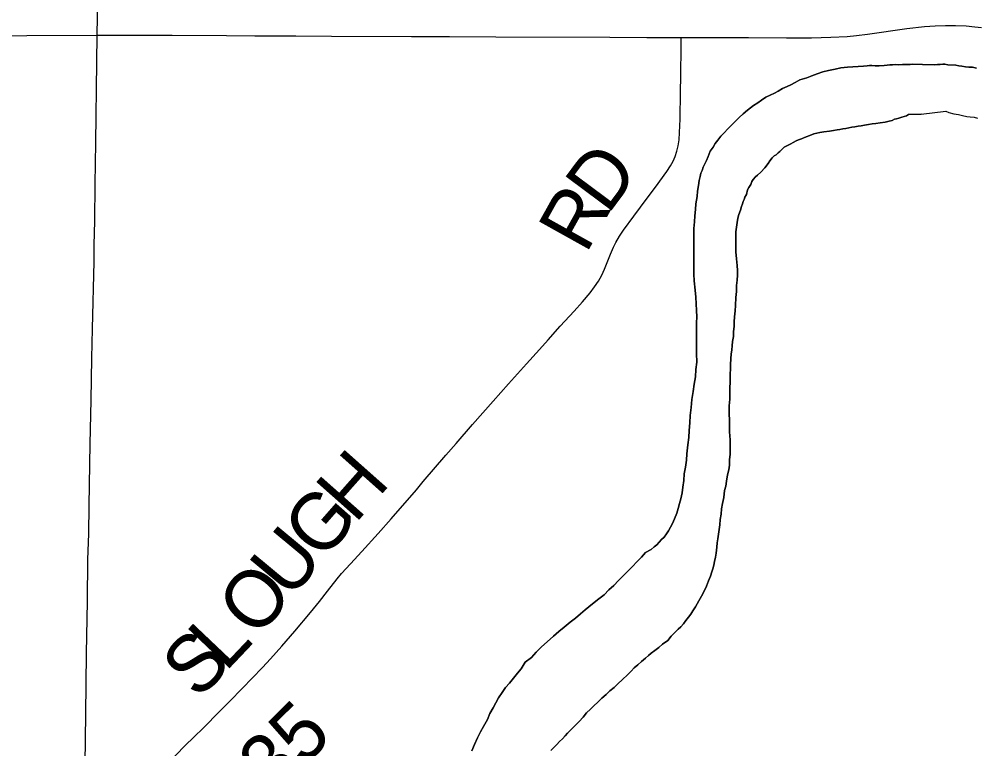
# Model space of a CAD drawing. Extents: x 2.1 to 73.9, y 4 to 26.
# Drawn here: x 45.0951 to 45.571, y 22.9914 to 23.3545 of the extents above; entities that cross this region are included whole.
import ezdxf

# ---------------------------------------------------------------- set-up
doc = ezdxf.new("R2010")
doc.units = 0
for name, color, linetype in [('GM_X_County_Road', 7, 'Continuous'), ('GM_X_Major_River', 7, 'Continuous'), ('GM_X_State_Route', 7, 'Continuous'), ('GM_X_Township_Road', 7, 'Continuous'), ('GM_X_Township_Road_Text', 7, 'Continuous')]:
    doc.layers.add(name, color=color, linetype=linetype)

msp = doc.modelspace()

# ---------------------------------------------------------------- linework, layer by layer
at = {"layer": 'GM_X_County_Road'}
for points in [[(45.13396, 23.34651), (45.13443, 23.37409), (45.135, 23.41791), (45.13565, 23.46205), (45.13596, 23.48723), (45.13647, 23.52204), (45.13721, 23.56151), (45.13784, 23.59569), (45.13829, 23.62739), (45.13897, 23.66314), (45.13954, 23.69017), (45.14, 23.71255), (45.14029, 23.72747), (45.14061, 23.74829), (45.14116, 23.77198), (45.14159, 23.79024), (45.14203, 23.81542), (45.14219, 23.82785), (45.14253, 23.84741)], [(45.12754, 22.94886), (45.12771, 22.95705), (45.12797, 22.98377), (45.12823, 23.00862), (45.12857, 23.03875), (45.12905, 23.06486), (45.12936, 23.08568), (45.12972, 23.09842), (45.12994, 23.11241), (45.13052, 23.14317), (45.13089, 23.16493), (45.1313, 23.18575), (45.13165, 23.20035), (45.13236, 23.23392), (45.13245, 23.24201), (45.13273, 23.25412), (45.13301, 23.27246), (45.13323, 23.29298), (45.13373, 23.33307), (45.13396, 23.34651)]]:
    msp.add_lwpolyline(points, dxfattribs=at)
at = {"layer": 'GM_X_Major_River'}
for points in [[(45.52139, 23.33129), (45.51968, 23.33151), (45.51854, 23.33153), (45.5174, 23.33136), (45.51549, 23.3312), (45.5075, 23.33056), (45.50426, 23.33024), (45.5014, 23.32971), (45.49815, 23.329), (45.49529, 23.32829), (45.49242, 23.32739), (45.48974, 23.32629), (45.48725, 23.32538), (45.48381, 23.32429), (45.48151, 23.323), (45.4794, 23.32189), (45.47748, 23.32097), (45.47519, 23.32006), (45.47307, 23.31876), (45.47116, 23.31765), (45.46905, 23.31674), (45.46694, 23.31563), (45.46482, 23.31414), (45.4629, 23.31285), (45.46079, 23.31155), (45.45771, 23.30932), (45.45559, 23.30745), (45.45366, 23.30558), (45.45173, 23.30371), (45.4496, 23.30166), (45.44786, 23.29979), (45.44631, 23.2981), (45.44457, 23.29623), (45.44302, 23.29435), (45.44166, 23.29267), (45.44068, 23.29078), (45.43913, 23.28891), (45.43814, 23.28626), (45.43734, 23.28418), (45.43656, 23.28249), (45.43577, 23.28079), (45.43517, 23.27928), (45.43458, 23.27796), (45.43417, 23.27626), (45.43376, 23.27417), (45.43334, 23.27171), (45.43292, 23.26887), (45.43268, 23.26621), (45.43206, 23.26261), (45.43182, 23.25977), (45.43158, 23.25673), (45.43135, 23.25369), (45.4311, 23.25028), (45.43104, 23.24629), (45.43098, 23.2423), (45.43099, 23.23128), (45.43112, 23.22767), (45.43126, 23.22425), (45.43176, 23.21968), (45.43208, 23.21625), (45.43222, 23.21283), (45.43236, 23.2096), (45.4325, 23.20637), (45.43245, 23.20333), (45.4324, 23.20029), (45.43236, 23.19744), (45.43231, 23.19459), (45.43246, 23.19155), (45.4324, 23.18813), (45.43252, 23.18376), (45.43209, 23.18016), (45.43184, 23.17655), (45.43121, 23.17295), (45.43077, 23.16916), (45.43014, 23.16518), (45.4297, 23.16119), (45.42925, 23.15721), (45.429, 23.15361), (45.42875, 23.14981), (45.42851, 23.14639), (45.42807, 23.1426), (45.42762, 23.13824), (45.42738, 23.13501), (45.42695, 23.1316), (45.42632, 23.12819), (45.42608, 23.12496), (45.42565, 23.12155), (45.42522, 23.11871), (45.42461, 23.11587), (45.424, 23.11341), (45.4232, 23.11095), (45.42259, 23.10868), (45.42141, 23.10585), (45.42042, 23.10358), (45.41944, 23.1017), (45.41846, 23.09981), (45.41748, 23.09831), (45.41632, 23.09681), (45.41497, 23.0955), (45.4138, 23.09419), (45.41264, 23.09288)], [(45.41264, 23.09288), (45.4138, 23.09419), (45.41497, 23.0955), (45.41632, 23.09681), (45.41748, 23.09831), (45.41846, 23.09981), (45.41944, 23.1017), (45.42042, 23.10358), (45.42141, 23.10585), (45.42259, 23.10868), (45.4232, 23.11095), (45.424, 23.11341), (45.42461, 23.11587), (45.42522, 23.11871), (45.42565, 23.12155), (45.42608, 23.12496), (45.42632, 23.12819), (45.42695, 23.1316), (45.42738, 23.13501), (45.42762, 23.13824), (45.42807, 23.1426), (45.42851, 23.14639), (45.42875, 23.14981), (45.429, 23.15361), (45.42925, 23.15721), (45.4297, 23.16119), (45.43014, 23.16518), (45.43077, 23.16916), (45.43121, 23.17295), (45.43184, 23.17655), (45.43209, 23.18016), (45.43252, 23.18376), (45.4324, 23.18813), (45.43246, 23.19155), (45.43231, 23.19459), (45.43236, 23.19744), (45.4324, 23.20029), (45.43245, 23.20333), (45.4325, 23.20637), (45.43236, 23.2096), (45.43222, 23.21283), (45.43208, 23.21625), (45.43176, 23.21968), (45.43126, 23.22425), (45.43112, 23.22767), (45.43099, 23.23128), (45.43098, 23.2423), (45.43104, 23.24629), (45.4311, 23.25028), (45.43135, 23.25369), (45.43158, 23.25673), (45.43182, 23.25977), (45.43206, 23.26261), (45.43268, 23.26621), (45.43292, 23.26887), (45.43334, 23.27171), (45.43376, 23.27417), (45.43417, 23.27626), (45.43458, 23.27796), (45.43517, 23.27928), (45.43577, 23.28079), (45.43656, 23.28249), (45.43734, 23.28418), (45.43814, 23.28626), (45.43913, 23.28891), (45.44068, 23.29078), (45.44166, 23.29267), (45.44302, 23.29435), (45.44457, 23.29623), (45.44631, 23.2981), (45.44786, 23.29979), (45.4496, 23.30166), (45.45173, 23.30371), (45.45366, 23.30558), (45.45559, 23.30745), (45.45771, 23.30932), (45.46079, 23.31155), (45.4629, 23.31285), (45.46482, 23.31414), (45.46694, 23.31563), (45.46905, 23.31674), (45.47116, 23.31765), (45.47307, 23.31876), (45.47519, 23.32006), (45.47748, 23.32097), (45.4794, 23.32189), (45.48151, 23.323), (45.48381, 23.32429), (45.48725, 23.32538), (45.48974, 23.32629), (45.49242, 23.32739), (45.49529, 23.32829), (45.49815, 23.329), (45.5014, 23.32971), (45.50426, 23.33024), (45.5075, 23.33056), (45.51549, 23.3312), (45.5174, 23.33136), (45.51854, 23.33153), (45.51968, 23.33151), (45.52139, 23.33129)], [(45.54486, 23.33196), (45.54004, 23.33214), (45.53871, 23.33197), (45.53681, 23.332), (45.53491, 23.33203), (45.53319, 23.33187), (45.53148, 23.33189), (45.52996, 23.33173), (45.52863, 23.33175), (45.52729, 23.33158), (45.52577, 23.33141), (45.52329, 23.33126), (45.52234, 23.33128), (45.52139, 23.33129)], [(45.52139, 23.33129), (45.52234, 23.33128), (45.52329, 23.33126), (45.52577, 23.33141), (45.52729, 23.33158), (45.52863, 23.33175), (45.52996, 23.33173), (45.53148, 23.33189), (45.53319, 23.33187), (45.53491, 23.33203), (45.53681, 23.332), (45.53871, 23.33197), (45.54004, 23.33214), (45.54486, 23.33196)], [(45.57178, 23.33017), (45.56989, 23.33059), (45.56799, 23.33064), (45.56629, 23.33087), (45.56458, 23.33111), (45.56307, 23.33134), (45.56155, 23.33156), (45.55757, 23.33185), (45.55606, 23.33208), (45.55511, 23.33211), (45.55378, 23.33195), (45.55245, 23.33198), (45.55093, 23.33183), (45.54486, 23.33196)], [(45.54486, 23.33196), (45.55093, 23.33183), (45.55245, 23.33198), (45.55378, 23.33195), (45.55511, 23.33211), (45.55606, 23.33208), (45.55757, 23.33185), (45.56155, 23.33156), (45.56307, 23.33134), (45.56458, 23.33111), (45.56629, 23.33087), (45.56799, 23.33064), (45.56989, 23.33059), (45.57178, 23.33017)], [(45.54429, 23.30717), (45.55661, 23.30871), (45.55812, 23.30811), (45.56057, 23.30747), (45.56284, 23.30704), (45.56492, 23.3066), (45.567, 23.30617), (45.5687, 23.30594), (45.57059, 23.3057), (45.57229, 23.30528)], [(45.54429, 23.30717), (45.55661, 23.30871), (45.55812, 23.30811), (45.56057, 23.30747), (45.56284, 23.30704), (45.56492, 23.3066), (45.567, 23.30617), (45.5687, 23.30594), (45.57059, 23.3057), (45.57229, 23.30528)], [(45.4488, 23.15462), (45.44867, 23.15842), (45.44873, 23.16203), (45.44897, 23.16545), (45.44902, 23.16868), (45.44906, 23.17134), (45.4491, 23.17362), (45.44914, 23.17589), (45.44917, 23.17798), (45.44939, 23.18026), (45.44924, 23.18254), (45.44948, 23.18558), (45.44971, 23.18786), (45.44993, 23.18994), (45.45015, 23.19203), (45.45037, 23.19411), (45.45079, 23.19658), (45.45083, 23.19905), (45.45106, 23.20151), (45.4511, 23.20398), (45.45133, 23.20645), (45.45157, 23.20929), (45.4518, 23.21195), (45.45205, 23.21594), (45.45229, 23.21897), (45.45234, 23.22201), (45.45257, 23.22467), (45.4528, 23.22713), (45.45283, 23.22941), (45.45268, 23.23189), (45.45236, 23.23531), (45.45203, 23.23874), (45.452, 23.24862), (45.45223, 23.25108), (45.45264, 23.25335), (45.45305, 23.25544), (45.45347, 23.25733), (45.45426, 23.25941), (45.45486, 23.2613), (45.45526, 23.26262), (45.45566, 23.26376), (45.45605, 23.2647), (45.45646, 23.26602), (45.45724, 23.26734), (45.45784, 23.26961), (45.45843, 23.27074), (45.45941, 23.27225), (45.46, 23.27376), (45.46059, 23.2747), (45.46175, 23.27601), (45.46271, 23.27694), (45.46445, 23.27843), (45.46638, 23.28049), (45.46813, 23.28275), (45.46891, 23.28406), (45.47008, 23.28556), (45.47104, 23.2865), (45.472, 23.28705), (45.47297, 23.28799), (45.47393, 23.28873), (45.47509, 23.28985), (45.47606, 23.29079), (45.47702, 23.29134), (45.47798, 23.2919), (45.47932, 23.29245), (45.48047, 23.29319), (45.482, 23.29392), (45.48315, 23.29448), (45.48468, 23.29502), (45.48621, 23.29557), (45.48966, 23.29703), (45.4908, 23.29739), (45.49233, 23.29775), (45.49386, 23.29811), (45.49577, 23.29846), (45.49862, 23.29879), (45.50053, 23.29914), (45.50244, 23.29949), (45.50377, 23.29966), (45.5053, 23.30001), (45.50682, 23.30018), (45.50969, 23.3007), (45.51121, 23.30087), (45.51293, 23.30122), (45.51445, 23.30139), (45.51598, 23.30174), (45.51808, 23.30209), (45.51979, 23.30244), (45.5217, 23.3026), (45.5238, 23.30295), (45.52627, 23.30329), (45.52837, 23.30383), (45.5299, 23.30418), (45.53105, 23.30473), (45.532, 23.30491), (45.53315, 23.30527), (45.53468, 23.30582), (45.53697, 23.30635), (45.53794, 23.30709), (45.54429, 23.30717)], [(45.54429, 23.30717), (45.53794, 23.30709), (45.53697, 23.30635), (45.53468, 23.30582), (45.53315, 23.30527), (45.532, 23.30491), (45.53105, 23.30473), (45.5299, 23.30418), (45.52837, 23.30383), (45.52627, 23.30329), (45.5238, 23.30295), (45.5217, 23.3026), (45.51979, 23.30244), (45.51808, 23.30209), (45.51598, 23.30174), (45.51445, 23.30139), (45.51293, 23.30122), (45.51121, 23.30087), (45.50969, 23.3007), (45.50682, 23.30018), (45.5053, 23.30001), (45.50377, 23.29966), (45.50244, 23.29949), (45.50053, 23.29914), (45.49862, 23.29879), (45.49577, 23.29846), (45.49386, 23.29811), (45.49233, 23.29775), (45.4908, 23.29739), (45.48966, 23.29703), (45.48621, 23.29557), (45.48468, 23.29502), (45.48315, 23.29448), (45.482, 23.29392), (45.48047, 23.29319), (45.47932, 23.29245), (45.47798, 23.2919), (45.47702, 23.29134), (45.47606, 23.29079), (45.47509, 23.28985), (45.47393, 23.28873), (45.47297, 23.28799), (45.472, 23.28705), (45.47104, 23.2865), (45.47008, 23.28556), (45.46891, 23.28406), (45.46813, 23.28275), (45.46638, 23.28049), (45.46445, 23.27843), (45.46271, 23.27694), (45.46175, 23.27601), (45.46059, 23.2747), (45.46, 23.27376), (45.45941, 23.27225), (45.45843, 23.27074), (45.45784, 23.26961), (45.45724, 23.26734), (45.45646, 23.26602), (45.45605, 23.2647), (45.45566, 23.26376), (45.45526, 23.26262), (45.45486, 23.2613), (45.45426, 23.25941), (45.45347, 23.25733), (45.45305, 23.25544), (45.45264, 23.25335), (45.45223, 23.25108), (45.452, 23.24862), (45.45203, 23.23874), (45.45236, 23.23531), (45.45268, 23.23189), (45.45283, 23.22941), (45.4528, 23.22713), (45.45257, 23.22467), (45.45234, 23.22201), (45.45229, 23.21897), (45.45205, 23.21594), (45.4518, 23.21195), (45.45157, 23.20929), (45.45133, 23.20645), (45.4511, 23.20398), (45.45106, 23.20151), (45.45083, 23.19905), (45.45079, 23.19658), (45.45037, 23.19411), (45.45015, 23.19203), (45.44993, 23.18994), (45.44971, 23.18786), (45.44948, 23.18558), (45.44924, 23.18254), (45.44939, 23.18026), (45.44917, 23.17798), (45.44914, 23.17589), (45.4491, 23.17362), (45.44906, 23.17134), (45.44902, 23.16868), (45.44897, 23.16545), (45.44873, 23.16203), (45.44867, 23.15842), (45.4488, 23.15462)], [(45.35987, 22.99054), (45.36142, 22.99204), (45.36277, 22.99354), (45.36412, 22.99504), (45.36567, 22.99634), (45.36702, 22.99784), (45.36818, 22.99915), (45.36953, 23.00046), (45.37398, 23.00495), (45.37592, 23.0072), (45.37766, 23.00926), (45.37959, 23.01113), (45.38133, 23.01281), (45.38326, 23.01468), (45.38519, 23.01655), (45.38732, 23.01842), (45.38925, 23.02029), (45.39137, 23.02196), (45.3933, 23.02383), (45.39542, 23.0257), (45.39812, 23.02832), (45.39986, 23.03), (45.40141, 23.03169), (45.40314, 23.03318), (45.40507, 23.03486), (45.407, 23.03654), (45.40854, 23.03784), (45.40989, 23.03896), (45.41162, 23.04026), (45.41355, 23.04175), (45.41548, 23.04343), (45.41817, 23.04529), (45.41973, 23.04754), (45.42108, 23.04885), (45.42224, 23.04997), (45.4232, 23.05091), (45.42455, 23.05203), (45.42591, 23.05353), (45.42707, 23.05522), (45.42843, 23.05691), (45.4296, 23.05841), (45.43057, 23.0601), (45.43193, 23.06198), (45.4335, 23.065), (45.43487, 23.06744), (45.43624, 23.06989), (45.43742, 23.07234), (45.43842, 23.07499), (45.4394, 23.07725), (45.44001, 23.07952), (45.4406, 23.08103), (45.44101, 23.08274), (45.44142, 23.08463), (45.44183, 23.08671), (45.44225, 23.0888), (45.44249, 23.09183), (45.44271, 23.09392), (45.44293, 23.09582), (45.44399, 23.10283), (45.44422, 23.10548), (45.44464, 23.10814), (45.44488, 23.11079), (45.4453, 23.11345), (45.44592, 23.11648), (45.44635, 23.11989), (45.44696, 23.12216), (45.44738, 23.12462), (45.4476, 23.12671), (45.44801, 23.12841), (45.44842, 23.13031), (45.44883, 23.13258), (45.44887, 23.13524), (45.44911, 23.13809), (45.44916, 23.14151), (45.44922, 23.14511), (45.4489, 23.14911), (45.4488, 23.15462)], [(45.4488, 23.15462), (45.4489, 23.14911), (45.44922, 23.14511), (45.44916, 23.14151), (45.44911, 23.13809), (45.44887, 23.13524), (45.44883, 23.13258), (45.44842, 23.13031), (45.44801, 23.12841), (45.4476, 23.12671), (45.44738, 23.12462), (45.44696, 23.12216), (45.44635, 23.11989), (45.44592, 23.11648), (45.4453, 23.11345), (45.44488, 23.11079), (45.44464, 23.10814), (45.44422, 23.10548), (45.44399, 23.10283), (45.44293, 23.09582), (45.44271, 23.09392), (45.44249, 23.09183), (45.44225, 23.0888), (45.44183, 23.08671), (45.44142, 23.08463), (45.44101, 23.08274), (45.4406, 23.08103), (45.44001, 23.07952), (45.4394, 23.07725), (45.43842, 23.07499), (45.43742, 23.07234), (45.43624, 23.06989), (45.43487, 23.06744), (45.4335, 23.065), (45.43193, 23.06198), (45.43057, 23.0601), (45.4296, 23.05841), (45.42843, 23.05691), (45.42707, 23.05522), (45.42591, 23.05353), (45.42455, 23.05203), (45.4232, 23.05091), (45.42224, 23.04997), (45.42108, 23.04885), (45.41973, 23.04754), (45.41817, 23.04529), (45.41548, 23.04343), (45.41355, 23.04175), (45.41162, 23.04026), (45.40989, 23.03896), (45.40854, 23.03784), (45.407, 23.03654), (45.40507, 23.03486), (45.40314, 23.03318), (45.40141, 23.03169), (45.39986, 23.03), (45.39812, 23.02832), (45.39542, 23.0257), (45.3933, 23.02383), (45.39137, 23.02196), (45.38925, 23.02029), (45.38732, 23.01842), (45.38519, 23.01655), (45.38326, 23.01468), (45.38133, 23.01281), (45.37959, 23.01113), (45.37766, 23.00926), (45.37592, 23.0072), (45.37398, 23.00495), (45.36953, 23.00046), (45.36818, 22.99915), (45.36702, 22.99784), (45.36567, 22.99634), (45.36412, 22.99504), (45.36277, 22.99354), (45.36142, 22.99204), (45.35987, 22.99054)], [(45.41264, 23.09288), (45.4113, 23.09195), (45.40975, 23.09064), (45.40707, 23.08916), (45.40494, 23.08673), (45.39817, 23.07981), (45.39585, 23.07756), (45.39353, 23.07513), (45.39121, 23.0727), (45.38871, 23.07046), (45.38639, 23.06802), (45.38369, 23.06598), (45.38061, 23.06356), (45.37695, 23.06057), (45.37463, 23.05852), (45.37213, 23.05647), (45.36943, 23.05442), (45.36654, 23.052), (45.36385, 23.04976), (45.36115, 23.04752), (45.35806, 23.04472), (45.35517, 23.04211), (45.35246, 23.03949), (45.35014, 23.03687), (45.34706, 23.03445), (45.34511, 23.03125), (45.34317, 23.029), (45.34123, 23.02656), (45.33929, 23.02412), (45.33735, 23.02187), (45.3356, 23.01943), (45.33385, 23.0168), (45.33248, 23.01435), (45.3311, 23.01171), (45.32954, 23.00889), (45.32835, 23.00605), (45.32639, 23.00248), (45.32483, 22.99984), (45.32326, 22.99683), (45.32188, 22.99362), (45.3205, 22.99041)], [(45.3205, 22.99041), (45.32188, 22.99362), (45.32326, 22.99683), (45.32483, 22.99984), (45.32639, 23.00248), (45.32835, 23.00605), (45.32954, 23.00889), (45.3311, 23.01171), (45.33248, 23.01435), (45.33385, 23.0168), (45.3356, 23.01943), (45.33735, 23.02187), (45.33929, 23.02412), (45.34123, 23.02656), (45.34317, 23.029), (45.34511, 23.03125), (45.34706, 23.03445), (45.35014, 23.03687), (45.35246, 23.03949), (45.35517, 23.04211), (45.35806, 23.04472), (45.36115, 23.04752), (45.36385, 23.04976), (45.36654, 23.052), (45.36943, 23.05442), (45.37213, 23.05647), (45.37463, 23.05852), (45.37695, 23.06057), (45.38061, 23.06356), (45.38369, 23.06598), (45.38639, 23.06802), (45.38871, 23.07046), (45.39121, 23.0727), (45.39353, 23.07513), (45.39585, 23.07756), (45.39817, 23.07981), (45.40494, 23.08673), (45.40707, 23.08916), (45.40975, 23.09064), (45.4113, 23.09195), (45.41264, 23.09288)]]:
    msp.add_lwpolyline(points, dxfattribs=at)
at = {"layer": 'GM_X_State_Route'}
msp.add_lwpolyline([(45.07158, 23.34624), (45.09893, 23.34644), (45.13396, 23.34651), (45.1412, 23.34653), (45.17135, 23.34649), (45.1984, 23.34634), (45.21238, 23.34628), (45.2329, 23.34628), (45.25062, 23.34612), (45.29041, 23.34594), (45.30937, 23.34587), (45.33238, 23.34582), (45.38926, 23.34564), (45.4076, 23.34546), (45.41693, 23.3454), (45.42476, 23.34539), (45.4421, 23.34537), (45.45827, 23.34535), (45.47722, 23.34526), (45.48966, 23.34528), (45.49931, 23.34552), (45.50739, 23.34595), (45.51205, 23.34635), (45.51762, 23.347), (45.53706, 23.34991), (45.54594, 23.35085), (45.55119, 23.35127), (45.55645, 23.35145), (45.5614, 23.35141), (45.56666, 23.35116), (45.57098, 23.35078), (45.57435, 23.35034)], dxfattribs=at)
at = {"layer": 'GM_X_Township_Road'}
msp.add_lwpolyline([(45.17254, 22.98776), (45.17824, 22.99348), (45.18156, 22.99675), (45.18733, 23.00239), (45.19435, 23.00939), (45.19979, 23.01493), (45.20628, 23.02163), (45.21105, 23.02652), (45.21623, 23.03189), (45.22028, 23.03617), (45.22587, 23.04241), (45.23243, 23.04987), (45.24017, 23.05917), (45.24461, 23.06477), (45.2486, 23.06993), (45.25345, 23.07599), (45.25566, 23.07861), (45.26003, 23.08347), (45.2657, 23.08964), (45.27383, 23.09862), (45.28026, 23.10579), (45.29295, 23.12026), (45.29627, 23.12436), (45.3076, 23.13759), (45.31274, 23.1434), (45.32081, 23.15286), (45.33114, 23.16447), (45.33879, 23.17305), (45.34775, 23.18297), (45.35427, 23.19006), (45.3586, 23.19493), (45.36446, 23.20178), (45.37152, 23.20923), (45.37565, 23.21385), (45.37942, 23.21836), (45.38165, 23.22132), (45.3835, 23.22415), (45.38517, 23.2271), (45.38659, 23.23017), (45.38963, 23.23764), (45.39109, 23.2411), (45.3922, 23.24335), (45.3941, 23.24659), (45.39602, 23.24945), (45.40113, 23.25651), (45.40786, 23.26545), (45.412, 23.2709), (45.41769, 23.27864), (45.41951, 23.28149), (45.42081, 23.28392), (45.42176, 23.28617), (45.42261, 23.28879), (45.42324, 23.29147), (45.4237, 23.29451), (45.424, 23.2982), (45.42425, 23.3047), (45.42446, 23.31837), (45.42454, 23.32614), (45.42476, 23.34105), (45.42476, 23.34198), (45.42476, 23.34539)], dxfattribs=at)

# ---------------------------------------------------------------- texts
at = {"layer": 'GM_X_Township_Road_Text'}
for s, height, rotation, p in [('D', 0.02841, 53.3559, (45.38817, 23.2568)), ('R', 0.02841, 60.8787, (45.37735, 23.23725)), ('H', 0.02841, 48.4382, (45.26229, 23.10301)), ('G', 0.02841, 48.8048, (45.24585, 23.08424)), ('U', 0.02841, 50.3153, (45.23002, 23.06515)), ('O', 0.02841, 49.2683, (45.21334, 23.04577)), ('L', 0.02841, 46.5004, (45.19771, 23.02924)), ('S', 0.02841, 46.0315, (45.18422, 23.01527)), ('T-135', 0.028409, 44.5941, (45.18117, 22.92753))]:
    msp.add_text(s, height=height, rotation=rotation, dxfattribs=at).set_placement(p)

doc.saveas('drawing.dxf')
